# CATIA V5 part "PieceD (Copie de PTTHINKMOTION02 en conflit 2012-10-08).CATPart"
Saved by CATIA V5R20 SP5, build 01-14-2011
Part number: PieceD
Bounding box of the stored display mesh (mm): x -20.997 to 20.997, y -20.998 to 20.998, z -63 to 10
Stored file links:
  D:\thinkmotion-MPB\Dropbox\IAO\IAO_2010\iao\IAO OK\IAO_2010_1447_melguidj\Catia_1447_melguidj\PieceD.CATPart
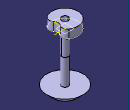
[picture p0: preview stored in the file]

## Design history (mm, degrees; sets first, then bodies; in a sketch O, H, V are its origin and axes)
Body1 (main body)
  Sketch1 on xy-plane, origin (0, 0, 0), H (1, 0, 0), V (0, 1, 0)
    point P1 (0, 0)
    point P2 (0, -12.5)
    circle A1 centre (0, 0) radius 4
    arc A2 centre (0, 0) radius 15 from (8, 12.6886) to (8, -12.6886) ccw
    axis line L1 (16.2484, 7.4881) -> (13.1511, 9.4409)
    point P5 (8, 12.6886)
    point P6 (8, -12.6886)
    arc A3 centre (4.8, 7.6131) radius 6 from (8, 12.6886) to (9.4379, 3.8066) cw
    arc A4 centre (14.0758, 0) radius 6 from (9.4379, 3.8066) to (9.4379, -3.8066) ccw
    arc A5 centre (4.8, -7.6131) radius 6 from (9.4379, -3.8066) to (8, -12.6886) cw
    point P12 (8, -12.6886)
    radius A1 = 4
    radius A2 = 15
    radius A3 = 6
    radius A4 = 6
    radius A5 = 6
    distance P5 V = 8
    distance P6 V = 8
    coincidence: P1 V, P2 V, P1 O, L1 P5, A5 P12, P12 A2
    tangency: L1 A2, A3 A2, A4 A3, A5 A4, A5 A2
    concentricity: A2 A1
  Pad1: profile Sketch1, direction (0, 0, 1), length 10
  Sketch2 on start face of Pad1, origin (0, 0, 0), H (1, 0, 0), V (0, -1, 0)
    circle A1 centre (0, 0) radius 4
    reference projected circle E1 centre (0, 0) radius 4 from edge [face of Pad1 from Sketch1.A1 | start face of Pad1]
    coincidence: A1 E1
  Pad2: profile Sketch2, direction (0, 0, -1), length 45
  Plane1: stored without definition
  DatumCurve1
  DatumCurve2
  Sketch3 on Plane1, origin (0, 0, 0), H (-0.2368, -0.9715, 0), V (0, 0, 1)
    point P1 (0, -26.0088)
    line L1 (0, -26.0088) -> (0, -63)
    line L2 (0, -63) -> (-14, -63)
    line L3 (-14, -63) -> (-21, -56)
    line L4 (-21, -56) -> (-4, -56)
    line L5 (-4, -56) -> (-4, -26.0088)
    line L6 (-4, -26.0088) -> (0, -26.0088)
    reference projected line E1 through (0, -77) direction (1, 0) from edge of DatumCurve2
    length L6 = 4
    angle L3 L2 = 45
    distance L2 E1 = 14
    distance L2 L4 = 7
    length L2 = 14
    coincidence: P1 V
    vertical: L1 V, L5 V
    horizontal: L2 H, L4 H, L6 H
  Shaft1: profile Sketch3, axis Sketch3.L1, angle 360
  Plane2: type Offset, RefPlane end face of Pad1, Offset 10
  Sketch4 on Plane2, origin (0, 0, 0), H (1, 0, 0), V (0, -1, 0)
    projected arc E1 centre (0, 0) radius 15 from (8, 12.6886) to (8, -12.6886) ccw from edge [face of Pad1 from Sketch1.A2 | end face of Pad1]
    projected arc E2 centre (4.8, -7.6131) radius 6 from (8, -12.6886) to (9.4379, -3.8066) ccw from edge [face of Pad1 from Sketch1.A3 | end face of Pad1]
    projected arc E3 centre (14.0758, 0) radius 6 from (9.4379, 3.8066) to (9.4379, -3.8066) ccw from edge [face of Pad1 from Sketch1.A4 | end face of Pad1]
    projected arc E4 centre (4.8, 7.6131) radius 6 from (9.4379, 3.8066) to (8, 12.6886) ccw from edge [face of Pad1 from Sketch1.A5 | end face of Pad1]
